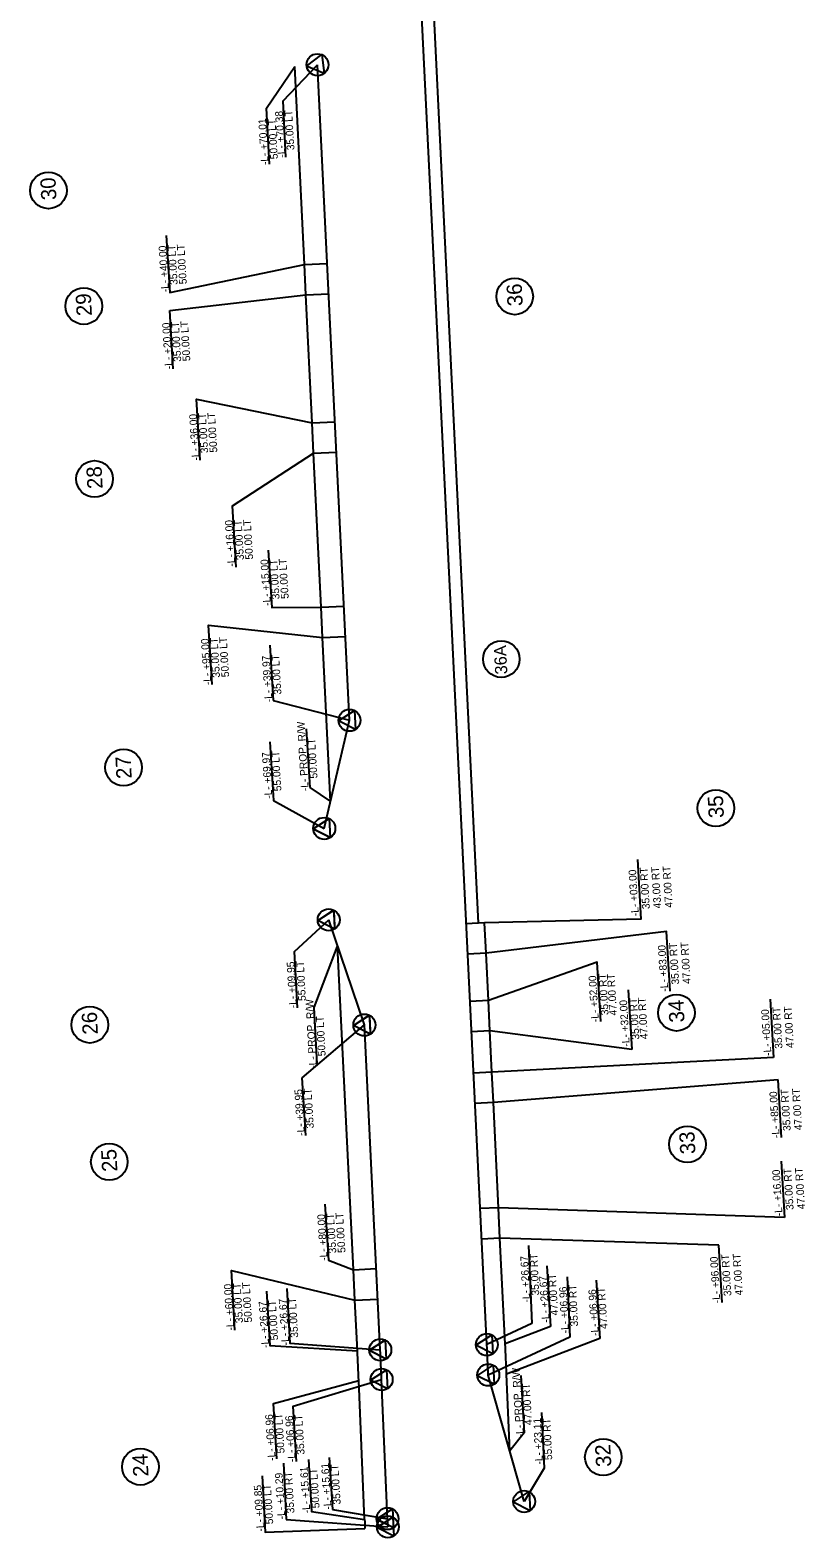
# Model space of a CAD drawing. Extents: x 2368169 to 2369183, y 801414 to 808542.
# Drawn here: x 2368573 to 2369082, y 803630 to 804618 of the extents above; entities that cross this region are included whole.
import ezdxf

# ---------------------------------------------------------------- set-up
doc = ezdxf.new("R2010")
doc.units = 0
for name, color, linetype in [('Prop Easement Construction', 7, 'Continuous'), ('Prop Easement Construction Station Offsets', 7, 'Continuous'), ('Prop Easement Permanent Drainage', 7, 'Continuous'), ('Prop Easement Permanent Drainage Station Offsets', 7, 'Continuous'), ('Prop Easement Permanent Drainage Utility', 7, 'Continuous'), ('Prop Easement Permanent Drainage Utility Station Offsets', 7, 'Continuous'), ('Prop Easement Permanent Utility', 7, 'Continuous'), ('Prop Easement Permanent Utility Station Offsets', 7, 'Continuous'), ('Prop Parcel Number CELL', 7, 'Continuous'), ('Prop Parcel Number Text', 7, 'Continuous'), ('Prop ROW Marker CELL', 7, 'Continuous'), ('Prop ROW RW Lines', 7, 'Continuous'), ('Prop ROW Station Offsets', 7, 'Continuous')]:
    doc.layers.add(name, color=color, linetype=linetype)

msp = doc.modelspace()

# ---------------------------------------------------------------- linework, layer by layer
at = {"layer": 'Prop Easement Construction'}
for p, q in [((2368849.63, 804398.47), (2368836.13, 804674.88)), ((2368867.5, 804032.82), (2368849.63, 804398.47)), ((2368873.98, 803982.08), (2368872.47, 804013.04)), ((2368876.27, 803935.13), (2368874.95, 803962.1)), ((2368880.61, 803846.24), (2368877.25, 803915.16)), ((2368884.97, 803757.01), (2368881.59, 803826.26)), ((2368888, 803686.74), (2368885.88, 803737))]:
    msp.add_line(p, q, dxfattribs=at)
msp.add_arc((2365928.41, 803612.59), 2960.09, 2.40884, 2.79656, dxfattribs=at)
at = {"layer": 'Prop Easement Construction Station Offsets'}
for p, q in [((2368912.33, 803808.16), (2368914.74, 803768.29)), ((2368944.65, 803798.7), (2368946.98, 803760.44)), ((2368914.74, 803768.29), (2368884.97, 803757.01)), ((2368946.98, 803760.44), (2368885.88, 803737))]:
    msp.add_line(p, q, dxfattribs=at)
msp.add_lwpolyline([(2368895.25, 803736.13), (2368897.53, 803698.59), (2368888, 803686.74)], dxfattribs=at)
at = {"layer": 'Prop Easement Permanent Drainage'}
for p, q in [((2368871.49, 804033.02), (2368859.51, 804032.43)), ((2368872.47, 804013.04), (2368871.49, 804033.02)), ((2368872.47, 804013.04), (2368860.48, 804012.45)), ((2368873.98, 803982.08), (2368861.99, 803981.49)), ((2368874.95, 803962.1), (2368873.98, 803982.08)), ((2368874.95, 803962.1), (2368862.97, 803961.51)), ((2368876.27, 803935.13), (2368864.29, 803934.55)), ((2368877.25, 803915.16), (2368876.27, 803935.13)), ((2368877.25, 803915.16), (2368865.26, 803914.57)), ((2368880.61, 803846.24), (2368868.63, 803845.65)), ((2368881.59, 803826.26), (2368880.61, 803846.24)), ((2368881.59, 803826.26), (2368869.6, 803825.68))]:
    msp.add_line(p, q, dxfattribs=at)
at = {"layer": 'Prop Easement Permanent Drainage Station Offsets'}
for p, q in [((2368965.71, 803989.07), (2368968.07, 803949.94)), ((2369058.66, 803983.02), (2369060.96, 803944.65)), ((2368968.07, 803949.94), (2368874.95, 803962.1)), ((2369060.96, 803944.65), (2368876.27, 803935.13)), ((2369064, 803930.05), (2368877.25, 803915.16)), ((2369066.28, 803892.25), (2369064, 803930.05)), ((2369065.98, 803876.67), (2369068.2, 803839.8)), ((2369068.2, 803839.8), (2368880.61, 803846.24)), ((2369025.07, 803821.76), (2368881.59, 803826.26)), ((2369027.34, 803783.95), (2369025.07, 803821.76))]:
    msp.add_line(p, q, dxfattribs=at)
for points in [[(2368971.67, 804074.57), (2368974.03, 804035.43), (2368871.49, 804033.02)], [(2368993.14, 803988.25), (2368990.79, 804027.36), (2368872.47, 804013.04)], [(2368947.69, 803968.23), (2368945.34, 804007.29), (2368873.98, 803982.08)]]:
    msp.add_lwpolyline(points, dxfattribs=at)
at = {"layer": 'Prop Easement Permanent Drainage Utility'}
for p, q in [((2368753.29, 804464.76), (2368768.27, 804465.49)), ((2368754.26, 804444.79), (2368753.29, 804464.76)), ((2368754.26, 804444.79), (2368769.24, 804445.52)), ((2368758.36, 804360.89), (2368773.34, 804361.62)), ((2368759.34, 804340.91), (2368758.36, 804360.89)), ((2368759.34, 804340.91), (2368774.32, 804341.64)), ((2368764.26, 804240.03), (2368779.25, 804240.76)), ((2368765.24, 804220.05), (2368764.26, 804240.03)), ((2368765.24, 804220.05), (2368780.22, 804220.79)), ((2368785.49, 803805.55), (2368800.47, 803806.28)), ((2368786.46, 803785.57), (2368785.49, 803805.55)), ((2368786.46, 803785.57), (2368801.44, 803786.3))]:
    msp.add_line(p, q, dxfattribs=at)
at = {"layer": 'Prop Easement Permanent Drainage Utility Station Offsets'}
for p, q in [((2368665.03, 804434.64), (2368754.26, 804444.79)), ((2368667.33, 804396.38), (2368665.03, 804434.64))]:
    msp.add_line(p, q, dxfattribs=at)
for points in [[(2368662.76, 804483.71), (2368665.01, 804446.4), (2368753.29, 804464.76)], [(2368685.03, 804336.45), (2368682.63, 804376.35), (2368758.36, 804360.89)], [(2368708.49, 804266.31), (2368706.07, 804306.52), (2368759.34, 804340.91)], [(2368729.6, 804277.46), (2368731.86, 804239.89), (2368764.26, 804240.03)], [(2368692.77, 804189.21), (2368690.43, 804228.25), (2368765.24, 804220.05)], [(2368766.83, 803848.58), (2368769.04, 803811.77), (2368785.49, 803805.55)], [(2368707.81, 803766.01), (2368705.46, 803805.06), (2368786.46, 803785.57)]]:
    msp.add_lwpolyline(points, dxfattribs=at)
at = {"layer": 'Prop Easement Permanent Utility'}
for p, q in [((2368753.29, 804464.76), (2368746.94, 804594.62)), ((2368758.36, 804360.89), (2368754.26, 804444.79)), ((2368764.26, 804240.03), (2368759.34, 804340.91)), ((2368770.49, 804112.65), (2368765.24, 804220.05)), ((2368785.49, 803805.55), (2368775.12, 804017.75)), ((2368788.09, 803752.28), (2368786.46, 803785.57)), ((2368792.81, 803641.66), (2368788.97, 803732.93))]:
    msp.add_line(p, q, dxfattribs=at)
for centre, radius, start, end in [((2365938.4, 803613.08), 2853.09, 2.40884, 2.79656), ((2372339.67, 803790.87), 3550, 182.40885, 182.50321)]:
    msp.add_arc(centre, radius, start, end, dxfattribs=at)
at = {"layer": 'Prop Easement Permanent Utility Station Offsets'}
for p, q in [((2368754.55, 804160.25), (2368756.86, 804121.81)), ((2368756.86, 804121.81), (2368770.49, 804112.65)), ((2368759.65, 803977.48), (2368775.12, 804017.75)), ((2368761.59, 803940.6), (2368759.65, 803977.48))]:
    msp.add_line(p, q, dxfattribs=at)
for points in [[(2368730.48, 804530.43), (2368728.55, 804567.31), (2368746.94, 804594.62)], [(2368728.55, 803791.58), (2368730.71, 803755.78), (2368788.09, 803752.28)], [(2368735.27, 803681.61), (2368733.08, 803717.92), (2368788.97, 803732.99)], [(2368755.93, 803681.08), (2368757.98, 803647.11), (2368792.81, 803641.66)], [(2368725.71, 803670.37), (2368727.65, 803633.42), (2368793.06, 803635.82)]]:
    msp.add_lwpolyline(points, dxfattribs=at)
at = {"layer": 'Prop Parcel Number CELL'}
for p, q in [((2368585.48, 804513.35), (2368585.48, 804513.35)), ((2368608.67, 804437.46), (2368608.67, 804437.46)), ((2368891.24, 804443.84), (2368891.24, 804443.84)), ((2368615.71, 804324.11), (2368615.71, 804324.11)), ((2368882.45, 804205.96), (2368882.45, 804205.96)), ((2368634.74, 804134.89), (2368634.74, 804134.89)), ((2369023.15, 804108.23), (2369023.15, 804108.23)), ((2368997.31, 803974.09), (2368997.31, 803974.09)), ((2368612.61, 803966.21), (2368612.61, 803966.21)), ((2369004.49, 803887.78), (2369004.49, 803887.78)), ((2368625.38, 803876.31), (2368625.38, 803876.31)), ((2368645.81, 803676.33), (2368645.81, 803676.33)), ((2368949.31, 803682.63), (2368949.31, 803682.63))]:
    msp.add_line(p, q, dxfattribs=at)
for centre in [(2368585.48, 804513.35), (2368608.67, 804437.46), (2368891.24, 804443.84), (2368615.71, 804324.11), (2368882.45, 804205.96), (2368634.74, 804134.89), (2369023.15, 804108.23), (2368997.31, 803974.09), (2368612.61, 803966.21), (2369004.49, 803887.78), (2368625.38, 803876.31), (2368645.81, 803676.33), (2368949.31, 803682.63)]:
    msp.add_circle(centre, 12, dxfattribs=at)
at = {"layer": 'Prop ROW Marker CELL'}
for p, q in [((2368761.91, 804595.72), (2368761.91, 804595.72)), ((2368761.91, 804595.72), (2368761.91, 804595.72)), ((2368782.91, 804165.82), (2368782.91, 804165.82)), ((2368782.91, 804165.82), (2368782.91, 804165.82)), ((2368766.34, 804094.93), (2368766.34, 804094.93)), ((2368766.34, 804094.93), (2368766.34, 804094.93)), ((2368769.27, 804034.98), (2368769.27, 804034.98)), ((2368769.27, 804034.98), (2368769.27, 804034.98)), ((2368792.66, 803966.04), (2368792.66, 803966.04)), ((2368792.66, 803966.04), (2368792.66, 803966.04)), ((2368872.99, 803756.43), (2368872.99, 803756.43)), ((2368872.99, 803756.43), (2368872.99, 803756.43)), ((2368803.07, 803753.01), (2368803.07, 803753.01)), ((2368803.07, 803753.01), (2368803.07, 803753.01)), ((2368873.89, 803736.5), (2368873.89, 803736.5)), ((2368873.89, 803736.5), (2368873.89, 803736.5)), ((2368803.95, 803733.56), (2368803.95, 803733.56)), ((2368803.95, 803733.56), (2368803.95, 803733.56)), ((2368897.4, 803653.57), (2368897.4, 803653.57)), ((2368897.4, 803653.57), (2368897.4, 803653.57)), ((2368807.79, 803642.29), (2368807.79, 803642.29)), ((2368807.79, 803642.29), (2368807.79, 803642.29)), ((2368808.02, 803636.92), (2368808.02, 803636.92)), ((2368808.02, 803636.92), (2368808.02, 803636.92))]:
    msp.add_line(p, q, dxfattribs=at)
for points in [[(2368766.27, 804589.98), (2368754.76, 804594.81), (2368764.69, 804602.38)], [(2368766.28, 804589.98), (2368754.77, 804594.8), (2368764.68, 804602.38)], [(2368786.78, 804159.74), (2368775.71, 804165.5), (2368786.22, 804172.23)], [(2368786.87, 804159.8), (2368775.72, 804165.39), (2368786.12, 804172.28)], [(2368770.22, 804088.85), (2368759.15, 804094.61), (2368769.66, 804101.34)], [(2368770.31, 804088.91), (2368759.16, 804094.5), (2368769.56, 804101.38)], [(2368773.15, 804028.9), (2368762.08, 804034.66), (2368772.59, 804041.39)], [(2368773.24, 804028.96), (2368762.09, 804034.55), (2368772.49, 804041.44)], [(2368796.54, 803959.96), (2368785.47, 803965.72), (2368795.98, 803972.45)], [(2368796.63, 803960.02), (2368785.48, 803965.61), (2368795.88, 803972.49)], [(2368807.04, 803746.99), (2368795.88, 803752.58), (2368806.29, 803759.47)], [(2368806.95, 803746.93), (2368795.88, 803752.69), (2368806.39, 803759.42)], [(2368876.96, 803750.4), (2368865.8, 803755.99), (2368876.21, 803762.88)], [(2368876.96, 803750.4), (2368865.8, 803755.99), (2368876.21, 803762.88)], [(2368807.83, 803727.47), (2368796.76, 803733.23), (2368807.27, 803739.96)], [(2368807.92, 803727.53), (2368796.77, 803733.12), (2368807.17, 803740.01)], [(2368877.86, 803730.48), (2368866.71, 803736.07), (2368877.11, 803742.95)], [(2368877.86, 803730.48), (2368866.71, 803736.07), (2368877.11, 803742.95)], [(2368901.37, 803647.54), (2368890.21, 803653.13), (2368900.62, 803660.02)], [(2368901.37, 803647.54), (2368890.21, 803653.13), (2368900.62, 803660.02)], [(2368811.67, 803636.21), (2368800.6, 803641.97), (2368811.11, 803648.7)], [(2368811.76, 803636.27), (2368800.61, 803641.86), (2368811.01, 803648.75)], [(2368811.9, 803630.84), (2368800.83, 803636.6), (2368811.34, 803643.33)], [(2368811.99, 803630.9), (2368800.84, 803636.49), (2368811.24, 803643.38)]]:
    msp.add_lwpolyline(points, close=True, dxfattribs=at)
for centre in [(2368761.91, 804595.72), (2368782.91, 804165.82), (2368766.34, 804094.93), (2368769.27, 804034.98), (2368792.66, 803966.04), (2368803.07, 803753.01), (2368872.99, 803756.43), (2368803.95, 803733.56), (2368873.89, 803736.5), (2368897.4, 803653.57), (2368807.79, 803642.29), (2368808.02, 803636.92)]:
    msp.add_circle(centre, 7.2, dxfattribs=at)
at = {"layer": 'Prop ROW RW Lines'}
for p, q in [((2368848.47, 804258.34), (2368828.14, 804674.49)), ((2368782.91, 804165.82), (2368761.91, 804595.72)), ((2368872.99, 803756.43), (2368848.47, 804258.34)), ((2368766.34, 804094.93), (2368782.91, 804165.82)), ((2368792.66, 803966.04), (2368769.27, 804034.98)), ((2368803.07, 803753.01), (2368792.66, 803966.04)), ((2368897.4, 803653.57), (2368873.89, 803736.5)), ((2368807.79, 803642.29), (2368803.95, 803733.56))]:
    msp.add_line(p, q, dxfattribs=at)
for centre, radius, start, end in [((2365928.41, 803612.59), 2948.09, 2.40884, 2.79656), ((2365928.41, 803612.59), 2878.09, 2.40884, 2.79656), ((2372339.67, 803790.87), 3535, 182.40885, 182.49592)]:
    msp.add_arc(centre, radius, start, end, dxfattribs=at)
at = {"layer": 'Prop ROW Station Offsets'}
for p, q in [((2368739.29, 804571.99), (2368761.91, 804595.72)), ((2368741.22, 804535.1), (2368739.29, 804571.99)), ((2368730.71, 804215.01), (2368732.88, 804178.91)), ((2368732.88, 804178.91), (2368782.91, 804165.82)), ((2368746.83, 804014.26), (2368769.27, 804034.98)), ((2368748.76, 803977.38), (2368746.83, 804014.26)), ((2368751.91, 803931.4), (2368792.66, 803966.04)), ((2368754.18, 803893.66), (2368751.91, 803931.4)), ((2368900.22, 803821.34), (2368902.52, 803770.22)), ((2368925.68, 803800.96), (2368927.47, 803761.24)), ((2368902.52, 803770.22), (2368872.99, 803756.43)), ((2368927.47, 803761.24), (2368873.89, 803736.5)), ((2368739.52, 803678.67), (2368741.45, 803641.72)), ((2368769.65, 803682.35), (2368771.69, 803648.37)), ((2368771.69, 803648.37), (2368807.79, 803642.29)), ((2368741.45, 803641.72), (2368808.02, 803636.92))]:
    msp.add_line(p, q, dxfattribs=at)
for points in [[(2368730.69, 804151.71), (2368733, 804113.28), (2368766.34, 804094.93)], [(2368741.72, 803793.26), (2368743.87, 803757.46), (2368803.07, 803753.01)], [(2368748.1, 803679.73), (2368745.92, 803716.04), (2368803.95, 803733.56)], [(2368908.83, 803711.85), (2368910.46, 803675.51), (2368897.4, 803653.57)]]:
    msp.add_lwpolyline(points, dxfattribs=at)

# ---------------------------------------------------------------- texts
at = {"layer": 'Prop Easement Construction Station Offsets'}
for s, p in [('-L- +26.67', (2368914.08, 803770.98)), ('47.00 RT', (2368919.81, 803775.69)), ('-L- +06.96', (2368946.36, 803762.28)), ('47.00 RT', (2368952.1, 803766.86)), ('-L- PROP. R/W', (2368897.2, 803695.76)), ('47.00 RT', (2368902.73, 803703.76))]:
    msp.add_text(s, height=5, rotation=93.47163, dxfattribs=at).set_placement(p)
at = {"layer": 'Prop Easement Permanent Drainage Station Offsets'}
for s, p in [('-L- +03.00', (2368972.65, 804037.47)), ('35.00 RT', (2368979.88, 804042.16)), ('43.00 RT', (2368987.37, 804042.61)), ('47.00 RT', (2368994.85, 804043.06)), ('-L- +83.00', (2368991.9, 803988.03)), ('35.00 RT', (2368999.14, 803992.71)), ('47.00 RT', (2369006.62, 803993.16)), ('-L- +52.00', (2368946.45, 803968.01)), ('35.00 RT', (2368952.81, 803972.57)), ('47.00 RT', (2368958.33, 803972.41)), ('35.00 RT', (2368973.02, 803956.59)), ('47.00 RT', (2368978.6, 803956.84)), ('-L- +32.00', (2368966.69, 803951.97)), ('-L- +05.00', (2369059.64, 803945.92)), ('35.00 RT', (2369066.87, 803950.61)), ('47.00 RT', (2369074.35, 803951.06)), ('35.00 RT', (2369072.27, 803896.71)), ('47.00 RT', (2369079.76, 803897.16)), ('-L- +85.00', (2369065.04, 803892.03)), ('-L- +16.00', (2369066.89, 803840.77)), ('35.00 RT', (2369074.15, 803844.86)), ('47.00 RT', (2369081.64, 803845.31)), ('35.00 RT', (2369033.34, 803788.42)), ('47.00 RT', (2369040.82, 803788.87)), ('-L- +96.00', (2369026.11, 803783.73))]:
    msp.add_text(s, height=5, rotation=93.44297, dxfattribs=at).set_placement(p)
at = {"layer": 'Prop Easement Permanent Drainage Utility Station Offsets'}
for s, p in [('-L- +40.00', (2368664.49, 804446.65)), ('35.00 LT', (2368670.21, 804451.54)), ('50.00 LT', (2368676.2, 804451.9)), ('50.00 LT', (2368678.55, 804401.45)), ('-L- +20.00', (2368666.84, 804396.2)), ('35.00 LT', (2368672.56, 804401.09)), ('-L- +36.00', (2368684.54, 804336.28)), ('35.00 LT', (2368690.26, 804341.17)), ('50.00 LT', (2368696.25, 804341.53)), ('-L- +16.00', (2368707.97, 804266.73)), ('35.00 LT', (2368713.72, 804271.03)), ('50.00 LT', (2368719.71, 804271.39)), ('-L- +15.00', (2368731.3, 804241)), ('35.00 LT', (2368737.05, 804245.29)), ('50.00 LT', (2368743.04, 804245.65)), ('35.00 LT', (2368698, 804193.92)), ('50.00 LT', (2368703.99, 804194.28)), ('-L- +95.00', (2368692.28, 804189.03)), ('-L- +80.00', (2368768.56, 803811.53)), ('35.00 LT', (2368774.27, 803816.42)), ('50.00 LT', (2368780.26, 803816.78)), ('-L- +60.00', (2368707.32, 803765.83)), ('35.00 LT', (2368713.04, 803770.72)), ('50.00 LT', (2368719.02, 803771.08))]:
    msp.add_text(s, height=5, rotation=93.44297, dxfattribs=at).set_placement(p)
at = {"layer": 'Prop Easement Permanent Utility Station Offsets'}
for s, rotation, p in [('-L- +70.01', 93.44297, (2368729.87, 804530.05)), ('50.00 LT', 93.44297, (2368735.9, 804533.96)), ('-L- PROP. R/W', 93.44297, (2368756.15, 804119.52)), ('50.00 LT', 93.44297, (2368761.91, 804127.83)), ('-L- PROP. R/W', 92.99787, (2368761.45, 803937.44)), ('50.00 LT', 92.99787, (2368767.27, 803945.7)), ('50.00 LT', 93.44297, (2368736.12, 803759.4)), ('-L- +26.67', 93.44297, (2368730.17, 803754.39)), ('-L- +06.96', 93.44297, (2368734.38, 803680.34)), ('50.00 LT', 93.44297, (2368740.35, 803685.23)), ('-L- +15.61', 93.44297, (2368757.2, 803645.94)), ('50.00 LT', 93.44297, (2368763.27, 803649.26)), ('-L- +09.85', 93.44297, (2368726.93, 803633.97)), ('50.00 LT', 93.44297, (2368732.9, 803638.77))]:
    msp.add_text(s, height=5, rotation=rotation, dxfattribs=at).set_placement(p)
at = {"layer": 'Prop Parcel Number Text'}
for s, height, p in [('30', 10, (2368590.8, 804507.2)), ('36', 10, (2368896.56, 804437.63)), ('29', 10, (2368614, 804431.22)), ('28', 10, (2368621.04, 804317.84)), ('36A', 8, (2368886.45, 804196.14)), ('27', 10, (2368640.12, 804127.71)), ('35', 10, (2369028.48, 804101.96)), ('26', 10, (2368617.93, 803960.01)), ('34', 10, (2369002.63, 803967.91)), ('33', 10, (2369009.81, 803881.57)), ('25', 10, (2368630.71, 803870.06)), ('32', 10, (2368954.63, 803676.5)), ('24', 10, (2368651.14, 803670.11))]:
    msp.add_text(s, height=height, rotation=92.99787, dxfattribs=at).set_placement(p)
at = {"layer": 'Prop ROW Station Offsets'}
for s, rotation, p in [('35.00 LT', 93.44297, (2368746.81, 804539.83)), ('-L- +70.38', 93.44297, (2368740.85, 804534.93)), ('-L- +39.97', 93.44297, (2368732.32, 804177.81)), ('35.00 LT', 93.44297, (2368738.28, 804182.83)), ('-L- +69.97', 93.44297, (2368732.3, 804114.52)), ('55.00 LT', 93.44297, (2368738.26, 804119.53)), ('-L- +09.95', 92.99787, (2368748.28, 803977.15)), ('55.00 LT', 92.99787, (2368754.29, 803981.91)), ('-L- +39.95', 93.44297, (2368753.56, 803893.5)), ('35.00 LT', 93.44297, (2368759.53, 803898.3)), ('35.00 RT', 92.57642, (2368907.32, 803788.76)), ('-L- +26.67', 92.57642, (2368901.27, 803784.13)), ('35.00 RT', 92.57642, (2368932.78, 803768.45)), ('-L- +26.67', 93.44297, (2368743.33, 803756.06)), ('35.00 LT', 93.44297, (2368749.29, 803761.08)), ('-L- +06.96', 92.57642, (2368926.72, 803763.95)), ('-L- +06.96', 93.44297, (2368747.49, 803679.51)), ('35.00 LT', 93.44297, (2368753.46, 803684.4)), ('-L- +23.11', 92.57642, (2368909.73, 803677.88)), ('55.00 RT', 92.57642, (2368915.85, 803680.81)), ('-L- +15.61', 93.44297, (2368771.07, 803648.39)), ('35.00 LT', 93.44297, (2368777.13, 803651.71)), ('-L- +10.29', 93.44297, (2368740.76, 803641.94)), ('35.00 RT', 93.44297, (2368746.78, 803645.91))]:
    msp.add_text(s, height=5, rotation=rotation, dxfattribs=at).set_placement(p)

doc.saveas('drawing.dxf')
